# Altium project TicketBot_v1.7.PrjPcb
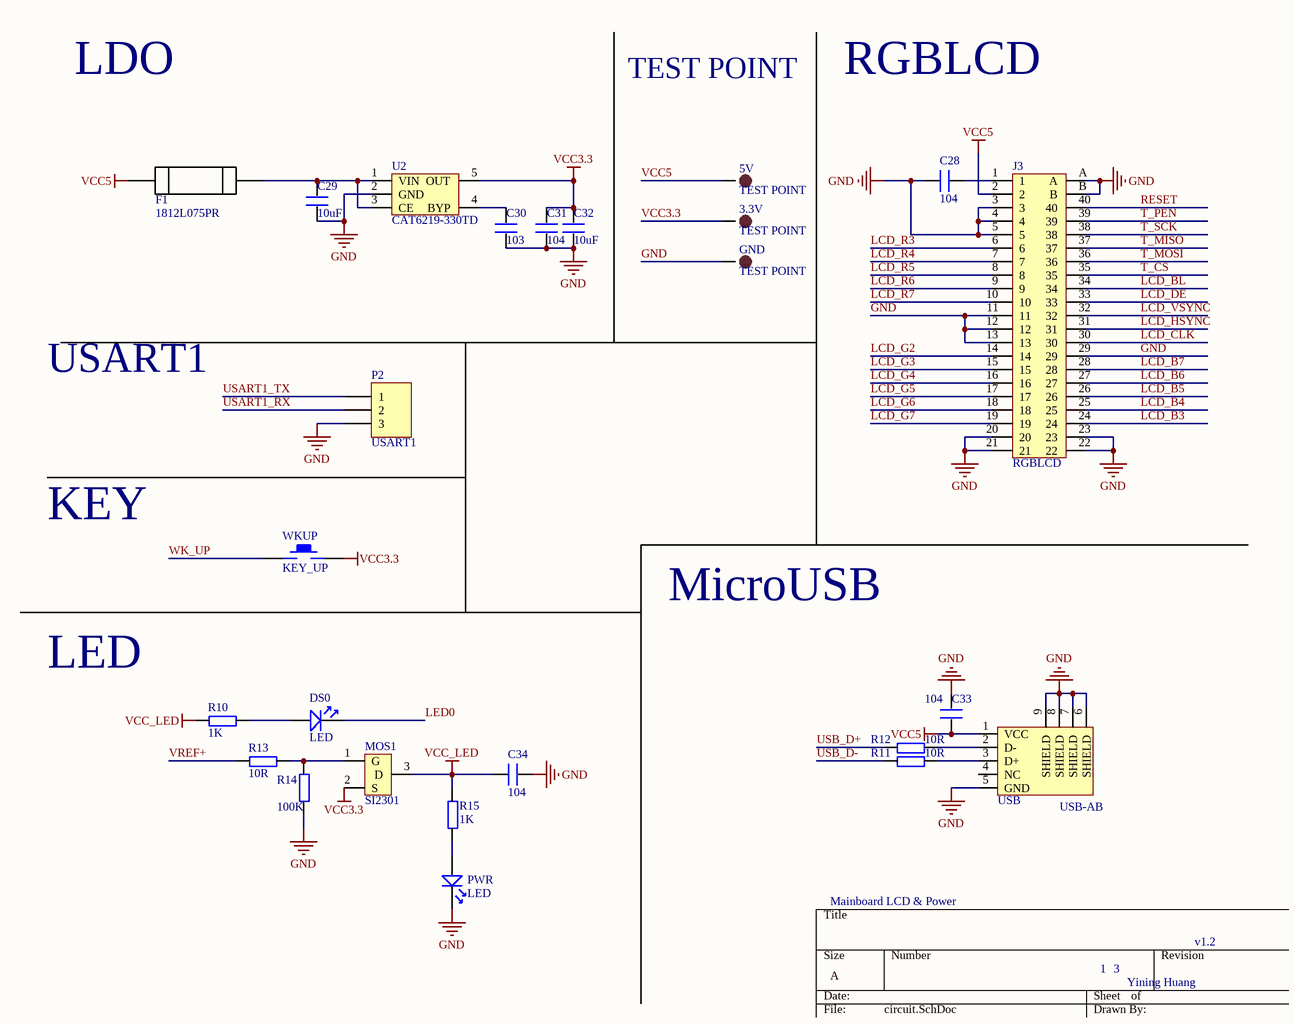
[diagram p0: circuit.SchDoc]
3 sheets, 90 parts. Net scope: global (net labels, ports and power ports of the same name join across sheets).
Board file: correctCore.PcbDoc
Sheets:
  circuit.SchDoc
  mem.SchDoc
  stm.SchDoc

## Sheet circuit.SchDoc
size A

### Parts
3.3V  TEST POINT  [TP-1.5]
5V  TEST POINT  [TP-1.5]
C28  104  [0805]
C29  10uF  [0805]
C30  103  [0805]
C31  104  [0805]
C32  10uF  [0805]
C33  104  [0805]
C34  104  [0805]
DS0  LED  [SMDLED-0603]
F1  1812L075PR  [*1812]
GND  TEST POINT  [TP-1.5]
J3  RGBLCD  [FPC-TOP40]
MOS1  SI2301  [SO-G3/C2.5]
P2  USART1  [HDR1X3]
PWR  LED  [SMDLED-0603]
R10  1K  [0805]
R11  10R  [0805]
R12  10R  [0805]
R13  10R  [0805]
R14  100K  [0805]
R15  1K  [0805]
U2  CAT6219-330TD  [SOT-23-5]
USB  USB-AB  [USB_AB - 5S - B]
WKUP  KEY_UP  [KEY_SOP3625]

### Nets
GND: C28.1 C29.1 C30.1 C31.1 C32.1 C33.2 C34.2 GND.1 J3.3 J3.4 J3.5 J3.11 J3.12 J3.13 J3.20 J3.21 J3.22 J3.23 J3.29 J3.A J3.B P2.3 PWR.2 R14.1 U2.2(GND) USB.5(GND) USB.6(SHIELD) USB.7(SHIELD) USB.8(SHIELD) USB.9(SHIELD)
VCC3.3: 3.3V.1 C31.2 C32.2 MOS1.2(S) U2.5(OUT) WKUP.2
VCC5: 5V.1 C33.1 F1.1 J3.2 USB.1(VCC)
VCC_LED: C34.1 MOS1.3(D) R10.1 R15.2
LCD_B3: J3.24
LCD_B4: J3.25
LCD_B5: J3.26
LCD_B6: J3.27
LCD_B7: J3.28
LCD_BL: J3.34
LCD_CLK: J3.30
LCD_DE: J3.33
LCD_G2: J3.14
LCD_G3: J3.15
LCD_G4: J3.16
LCD_G5: J3.17
LCD_G6: J3.18
LCD_G7: J3.19
LCD_HSYNC: J3.31
LCD_R3: J3.6
LCD_R4: J3.7
LCD_R5: J3.8
LCD_R6: J3.9
LCD_R7: J3.10
LCD_VSYNC: J3.32
LED0: DS0.2
RESET: J3.40
T_CS: J3.35  [project net PI8]
T_MISO: J3.37  [project net PG3]
T_MOSI: J3.36  [project net PI3]
T_PEN: J3.39  [project net PH7]
T_SCK: J3.38  [project net PH6]
USART1_RX: P2.2  [project net PA10]
USART1_TX: P2.1  [project net PA9]
USB_D+: R12.1  [project net PA12]
USB_D-: R11.1  [project net PA11]
VREF+: R13.1
WK_UP: WKUP.1  [project net PA0]
NetC28_2: C28.2 J3.1
NetC29_2: C29.2 F1.2 U2.1(VIN) U2.3(CE)
NetC30_2: C30.2 U2.4(BYP)
NetDS0_1: DS0.1 R10.2
NetMOS1_1: MOS1.1(G) R13.2 R14.2
NetPWR_1: PWR.1 R15.1
NetR11_2: R11.2 USB.3(D+)
NetR12_2: R12.2 USB.2(D-)

Not connected (* = marked no-connect by the designer): USB 4(NC)

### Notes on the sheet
- LDO
- TEST POINT
- RGBLCD
- USART1
- KEY
- MicroUSB
- LED
- Mainboard LCD & Power
- 1
- 3
- v1.2
- Yining Huang

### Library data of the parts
3.3V 5V GND = TEST-POINT: 测试点
C28-C34 = C
F1 = 1812L075PR: PTC Resettable Fuse 0.75A_hold_ 1.5A_trip_ 13.2VDC 100A 0.8W 0.2s 0.1Ohm SMD Solder Pad 1812 T/R; MF: Littelfuse Inc.
J3 = FPC-40: FPC-40P-0.5mm
MOS1 = MOS-P: IRLML6401/SI2301
P2 = Header 3: Header, 3-Pin
R10-R15 = R
U2 = CAT6219-330TD: 3.3V 500mA LDO
USB = USB-AB: MicroUSB
WKUP = KEY_M

## Sheet mem.SchDoc
size A
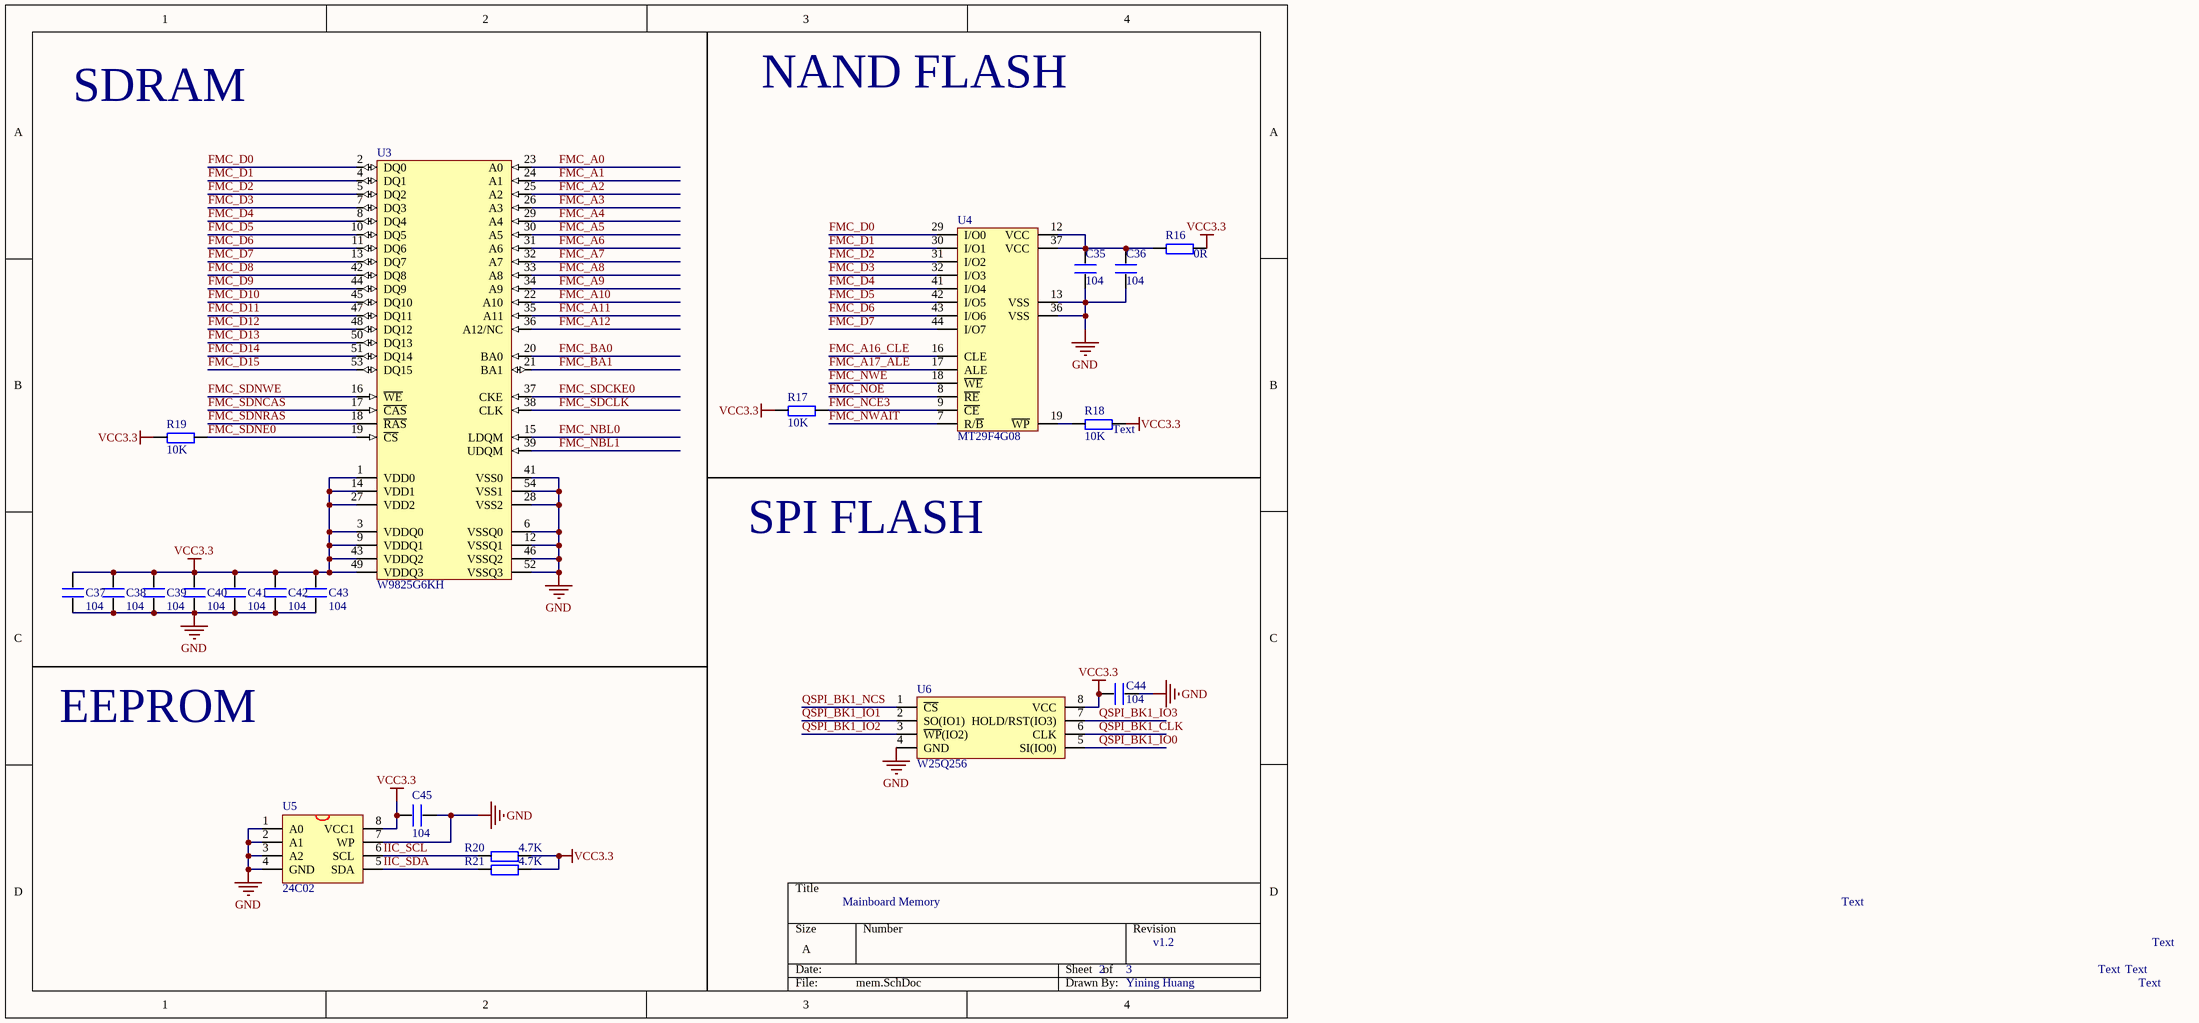
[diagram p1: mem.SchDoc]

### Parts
C35  104  [0805]
C36  104  [0805]
C37  104  [0805]
C38  104  [0805]
C39  104  [0805]
C40  104  [0805]
C41  104  [0805]
C42  104  [0805]
C43  104  [0805]
C44  104  [0805]
C45  104  [0805]
R16  0R  [0805]
R17  10K  [0805]
R18  10K  [0805]
R19  10K  [0805]
R20  4.7K  [0805]
R21  4.7K  [0805]
U3  W9825G6KH  [TSOP54]
U4  MT29F4G08  [TSOP48]
U5  24C02  [SOP-8]
U6  W25Q256  [WSON8]

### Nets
GND: C35.1 C36.1 C37.1 C38.1 C39.1 C40.1 C41.1 C42.1 C43.1 C44.2 C45.2 U3.6(VSSQ0) U3.12(VSSQ1) U3.28(VSS2) U3.41(VSS0) U3.46(VSSQ2) U3.52(VSSQ3) U3.54(VSS1) U4.13(VSS) U4.36(VSS) U5.1(A0) U5.2(A1) U5.3(A2) U5.4(GND) U5.7(WP) U6.4(GND)
VCC3.3: C37.2 C38.2 C39.2 C40.2 C41.2 C42.2 C43.2 C44.1 C45.1 R16.2 R17.1 R18.2 R19.1 R20.2 R21.2 U3.1(VDD0) U3.3(VDDQ0) U3.9(VDDQ1) U3.14(VDD1) U3.27(VDD2) U3.43(VDDQ2) U3.49(VDDQ3) U5.8(VCC1) U6.8(VCC)
FMC_A0: U3.23(A0)
FMC_A1: U3.24(A1)
FMC_A2: U3.25(A2)
FMC_A3: U3.26(A3)
FMC_A4: U3.29(A4)
FMC_A5: U3.30(A5)
FMC_A6: U3.31(A6)
FMC_A7: U3.32(A7)
FMC_A8: U3.33(A8)
FMC_A9: U3.34(A9)
FMC_A10: U3.22(A10)
FMC_A11: U3.35(A11)
FMC_A12: U3.36(A12/NC)
FMC_A16_CLE: U4.16(CLE)
FMC_A17_ALE: U4.17(ALE)
FMC_BA0: U3.20(BA0)
FMC_BA1: U3.21(BA1)
FMC_D0: U3.2(DQ0) U4.29(I/O0)
FMC_D1: U3.4(DQ1) U4.30(I/O1)
FMC_D2: U3.5(DQ2) U4.31(I/O2)
FMC_D3: U3.7(DQ3) U4.32(I/O3)
FMC_D4: U3.8(DQ4) U4.41(I/O4)
FMC_D5: U3.10(DQ5) U4.42(I/O5)
FMC_D6: U3.11(DQ6) U4.43(I/O6)
FMC_D7: U3.13(DQ7) U4.44(I/O7)
FMC_D8: U3.42(DQ8)
FMC_D9: U3.44(DQ9)
FMC_D10: U3.45(DQ10)
FMC_D11: U3.47(DQ11)
FMC_D12: U3.48(DQ12)
FMC_D13: U3.50(DQ13)
FMC_D14: U3.51(DQ14)
FMC_D15: U3.53(DQ15)
FMC_NBL0: U3.15(LDQM)
FMC_NBL1: U3.39(UDQM)
FMC_NCE3: R17.2 U4.9(~{CE})
FMC_NOE: U4.8(~{RE})
FMC_NWAIT: U4.7(R/~{B})
FMC_NWE: U4.18(~{WE})
FMC_SDCKE0: U3.37(CKE)
FMC_SDCLK: U3.38(CLK)
FMC_SDNCAS: U3.17(~{CAS})
FMC_SDNE0: R19.2 U3.19(~{CS})
FMC_SDNRAS: U3.18(~{RAS})
FMC_SDNWE: U3.16(~{WE})
IIC_SCL: R20.1 U5.6(SCL)
IIC_SDA: R21.1 U5.5(SDA)
QSPI_BK1_CLK: U6.6(CLK)  [project net PB2]
QSPI_BK1_IO0: U6.5(SI(IO0))  [project net PF8]
QSPI_BK1_IO1: U6.2(SO(IO1))  [project net PF9]
QSPI_BK1_IO2: U6.3(~{WP}(IO2))  [project net PF7]
QSPI_BK1_IO3: U6.7(HOLD/RST(IO3))  [project net PF6]
QSPI_BK1_NCS: U6.1(~{CS})  [project net PB6]
NetC35_2: C35.2 C36.2 R16.1 U4.12(VCC) U4.37(VCC)
NetR18_1: R18.1 U4.19(~{WP})

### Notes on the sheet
- NAND FLASH
- SDRAM
- (near R18) Text
- SPI FLASH
- EEPROM
- Mainboard Memory
- Text
- 2
- 3
- v1.2
- Yining Huang

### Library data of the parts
C35-C45 = C
R16-R21 = R
U3 = IS42S16160B: 32MB SDRAM
U4 = K9F2G08U0C: 256MB NAND FLASH
U5 = 24C256: EEPROM
U6 = W25Q128

## Sheet stm.SchDoc
size Tabloid
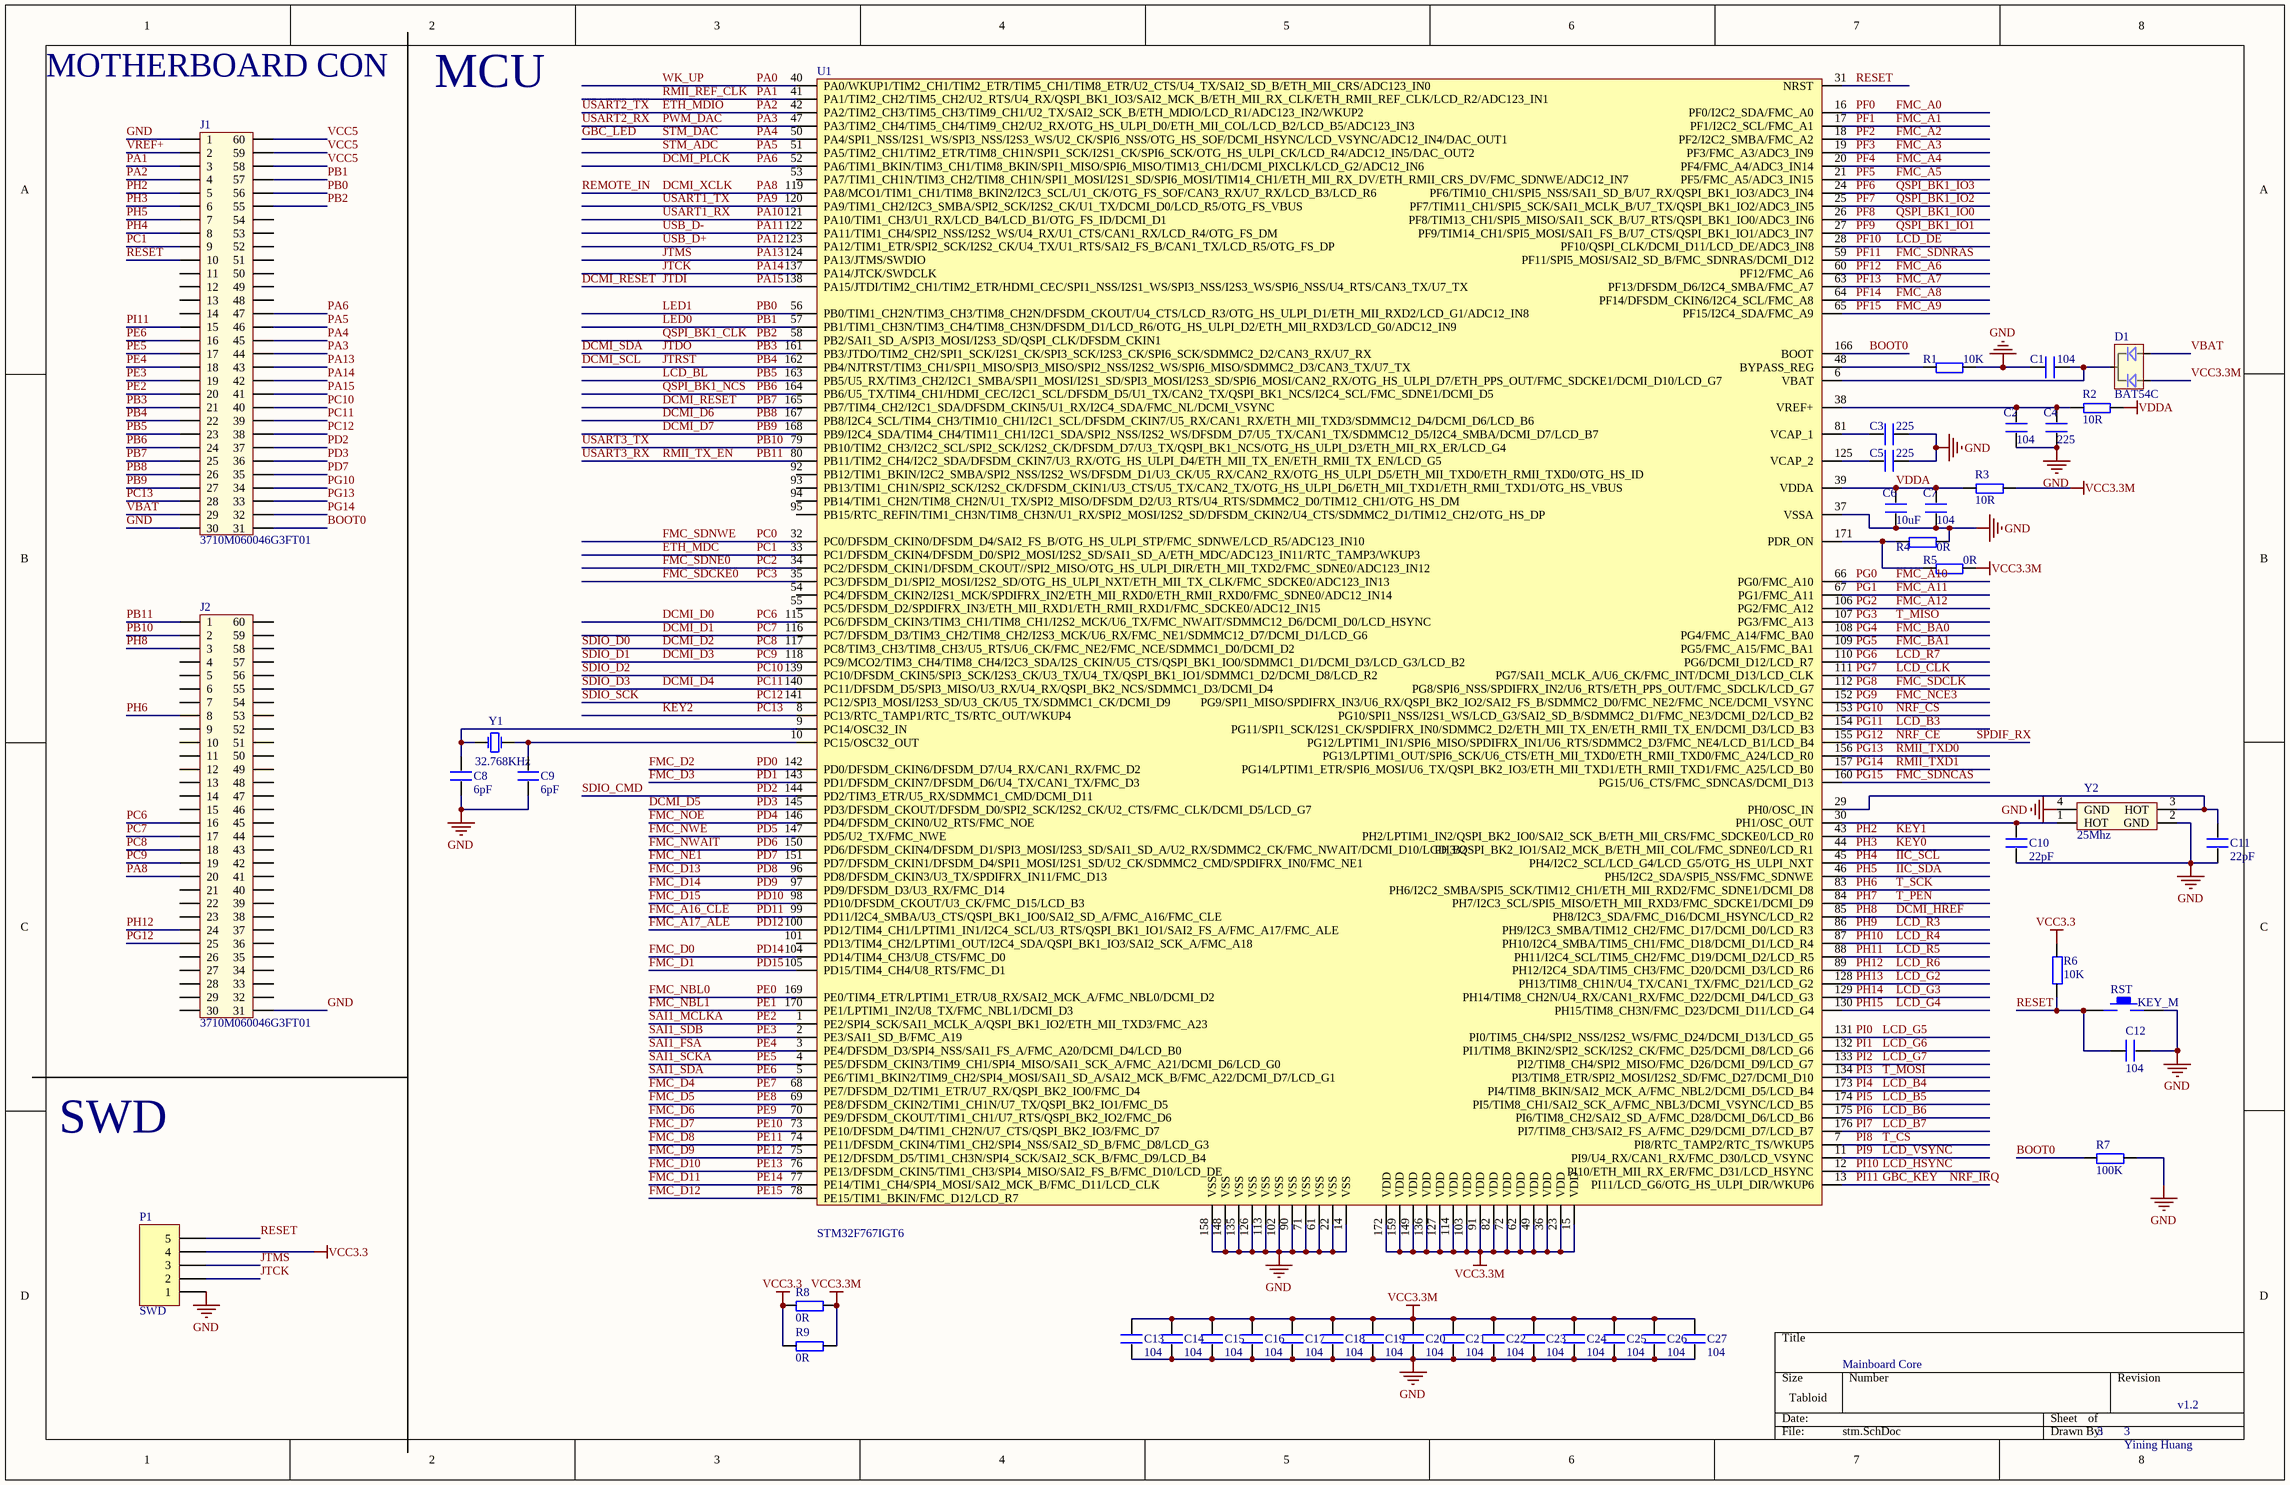
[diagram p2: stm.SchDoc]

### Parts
C1  104  [0805]
C2  104  [0805]
C3  225  [0805]
C4  225  [0805]
C5  225  [0805]
C6  10uF  [0805]
C7  104  [0805]
C8  6pF  [0805]
C9  6pF  [0805]
C10  22pF  [0805]
C11  22pF  [0805]
C12  104  [0805]
C13  104  [0805]
C14  104  [0805]
C15  104  [0805]
C16  104  [0805]
C17  104  [0805]
C18  104  [0805]
C19  104  [0805]
C20  104  [0805]
C21  104  [0805]
C22  104  [0805]
C23  104  [0805]
C24  104  [0805]
C25  104  [0805]
C26  104  [0805]
C27  104  [0805]
D1  BAT54C  [SOT-23]
J1  3710M060046G3FT01  [3710F060046G3FT01]
J2  3710M060046G3FT01  [3710F060046G3FT01]
P1  SWD  [HDR1X5]
R1  10K  [0805]
R2  10R  [0805]
R3  10R  [0805]
R4  0R  [0805]
R5  0R  [0805]
R6  10K  [0805]
R7  100K  [0805]
R8  0R  [0805]
R9  0R  [0805]
RST  KEY_M  [KEY_SOP3625]
U1  STM32F767IGT6  [LQFP176]
Y1  32.768KHz  [XTAL3215]
Y2  25Mhz  [XTAL3225]

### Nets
GND: C1.2 C2.1 C3.2 C4.1 C5.2 C6.1 C7.1 C8.1 C9.1 C10.1 C11.1 C12.2 C13.1 C14.1 C15.1 C16.1 C17.1 C18.1 C19.1 C20.1 C21.1 C22.1 C23.1 C24.1 C25.1 C26.1 C27.1 J1.1 J1.30 J2.31 P1.1 R1.2 R4.2 R7.2 RST.2 U1.14(VSS) U1.22(VSS) U1.37(VSSA) U1.61(VSS) U1.71(VSS) U1.90(VSS) U1.102(VSS) U1.113(VSS) U1.126(VSS) U1.135(VSS) U1.148(VSS) U1.158(VSS) Y2.2(GND) Y2.4(GND)
VCC3.3: P1.4 R6.2 R8.1 R9.1
VCC3.3M: C13.2 C14.2 C15.2 C16.2 C17.2 C18.2 C19.2 C20.2 C21.2 C22.2 C23.2 C24.2 C25.2 C26.2 C27.2 D1.1 R3.2 R5.2 R8.2 R9.2 U1.15(VDD) U1.23(VDD) U1.36(VDD) U1.49(VDD) U1.62(VDD) U1.72(VDD) U1.82(VDD) U1.91(VDD) U1.103(VDD) U1.114(VDD) U1.127(VDD) U1.136(VDD) U1.149(VDD) U1.159(VDD) U1.172(VDD)
VCC5: J1.58 J1.59 J1.60
VDDA: C6.2 C7.2 R2.2 R3.1 U1.39(VDDA)
BOOT0: J1.31 R7.1 U1.166(BOOT)
DCMI_D0: J2.16 U1.115(PC6/DFSDM_CKIN3/TIM3_CH1/TIM8_CH1/I2S2_MCK/U6_TX/FMC_NWAIT/SDMMC12_D6/DCMI_D0/LCD_HSYNC)  [also labelled PC6]
DCMI_D1: J2.17 U1.116(PC7/DFSDM_D3/TIM3_CH2/TIM8_CH2/I2S3_MCK/U6_RX/FMC_NE1/SDMMC12_D7/DCMI_D1/LCD_G6)  [also labelled PC7]
DCMI_D2: J2.18 U1.117(PC8/TIM3_CH3/TIM8_CH3/U5_RTS/U6_CK/FMC_NE2/FMC_NCE/SDMMC1_D0/DCMI_D2)  [also labelled PC8, SDIO_D0]
DCMI_D3: J2.19 U1.118(PC9/MCO2/TIM3_CH4/TIM8_CH4/I2C3_SDA/I2S_CKIN/U5_CTS/QSPI_BK1_IO0/SDMMC1_D1/DCMI_D3/LCD_G3/LCD_B2)  [also labelled PC9, SDIO_D1]
DCMI_D4: J1.39 U1.140(PC11/DFSDM_D5/SPI3_MISO/U3_RX/U4_RX/QSPI_BK2_NCS/SDMMC1_D3/DCMI_D4)  [also labelled PC11, SDIO_D3]
DCMI_D5: J1.36 U1.145(PD3/DFSDM_CKOUT/DFSDM_D0/SPI2_SCK/I2S2_CK/U2_CTS/FMC_CLK/DCMI_D5/LCD_G7)  [also labelled PD3]
DCMI_D6: J1.26 U1.167(PB8/I2C4_SCL/TIM4_CH3/TIM10_CH1/I2C1_SCL/DFSDM_CKIN7/U5_RX/CAN1_RX/ETH_MII_TXD3/SDMMC12_D4/DCMI_D6/LCD_B6)  [also labelled PB8]
DCMI_D7: J1.27 U1.168(PB9/I2C4_SDA/TIM4_CH4/TIM11_CH1/I2C1_SDA/SPI2_NSS/I2S2_WS/DFSDM_D7/U5_TX/CAN1_TX/SDMMC12_D5/I2C4_SMBA/DCMI_D7/LCD_B7)  [also labelled PB9]
DCMI_HREF: J2.3 U1.85(PH8/I2C3_SDA/FMC_D16/DCMI_HSYNC/LCD_R2)  [also labelled PH8]
DCMI_PLCK: J1.47 U1.52(PA6/TIM1_BKIN/TIM3_CH1/TIM8_BKIN/SPI1_MISO/SPI6_MISO/TIM13_CH1/DCMI_PIXCLK/LCD_G2/ADC12_IN6)  [also labelled PA6]
DCMI_RESET: J1.25 J1.41 U1.138(PA15/JTDI/TIM2_CH1/TIM2_ETR/HDMI_CEC/SPI1_NSS/I2S1_WS/SPI3_NSS/I2S3_WS/SPI6_NSS/U4_RTS/CAN3_TX/U7_TX) U1.165(PB7/TIM4_CH2/I2C1_SDA/DFSDM_CKIN5/U1_RX/I2C4_SDA/FMC_NL/DCMI_VSYNC)  [also labelled JTDI, PA15, PB7]
DCMI_SCL: J1.22 U1.162(PB4/NJTRST/TIM3_CH1/SPI1_MISO/SPI3_MISO/SPI2_NSS/I2S2_WS/SPI6_MISO/SDMMC2_D3/CAN3_TX/U7_TX)  [also labelled JTRST, PB4]
DCMI_SDA: J1.21 U1.161(PB3/JTDO/TIM2_CH2/SPI1_SCK/I2S1_CK/SPI3_SCK/I2S3_CK/SPI6_SCK/SDMMC2_D2/CAN3_RX/U7_RX)  [also labelled JTDO, PB3]
DCMI_XCLK: J2.20 U1.119(PA8/MCO1/TIM1_CH1/TIM8_BKIN2/I2C3_SCL/U1_CK/OTG_FS_SOF/CAN3_RX/U7_RX/LCD_B3/LCD_R6)  [also labelled PA8, REMOTE_IN]
ETH_MDC: J1.9 U1.33(PC1/DFSDM_CKIN4/DFSDM_D0/SPI2_MOSI/I2S2_SD/SAI1_SD_A/ETH_MDC/ADC123_IN11/RTC_TAMP3/WKUP3)  [also labelled PC1]
ETH_MDIO: J1.4 U1.42(PA2/TIM2_CH3/TIM5_CH3/TIM9_CH1/U2_TX/SAI2_SCK_B/ETH_MDIO/LCD_R1/ADC123_IN2/WKUP2)  [also labelled PA2, USART2_TX]
FMC_A0: U1.16(PF0/I2C2_SDA/FMC_A0)  [also labelled PF0]
FMC_A1: U1.17(PF1/I2C2_SCL/FMC_A1)  [also labelled PF1]
FMC_A2: U1.18(PF2/I2C2_SMBA/FMC_A2)  [also labelled PF2]
FMC_A3: U1.19(PF3/FMC_A3/ADC3_IN9)  [also labelled PF3]
FMC_A4: U1.20(PF4/FMC_A4/ADC3_IN14)  [also labelled PF4]
FMC_A5: U1.21(PF5/FMC_A5/ADC3_IN15)  [also labelled PF5]
FMC_A6: U1.60(PF12/FMC_A6)  [also labelled PF12]
FMC_A7: U1.63(PF13/DFSDM_D6/I2C4_SMBA/FMC_A7)  [also labelled PF13]
FMC_A8: U1.64(PF14/DFSDM_CKIN6/I2C4_SCL/FMC_A8)  [also labelled PF14]
FMC_A9: U1.65(PF15/I2C4_SDA/FMC_A9)  [also labelled PF15]
FMC_A10: U1.66(PG0/FMC_A10)  [also labelled PG0]
FMC_A11: U1.67(PG1/FMC_A11)  [also labelled PG1]
FMC_A12: U1.106(PG2/FMC_A12)  [also labelled PG2]
FMC_A16_CLE: U1.99(PD11/I2C4_SMBA/U3_CTS/QSPI_BK1_IO0/SAI2_SD_A/FMC_A16/FMC_CLE)  [also labelled PD11]
FMC_A17_ALE: U1.100(PD12/TIM4_CH1/LPTIM1_IN1/I2C4_SCL/U3_RTS/QSPI_BK1_IO1/SAI2_FS_A/FMC_A17/FMC_ALE)  [also labelled PD12]
FMC_BA0: U1.108(PG4/FMC_A14/FMC_BA0)  [also labelled PG4]
FMC_BA1: U1.109(PG5/FMC_A15/FMC_BA1)  [also labelled PG5]
FMC_D0: U1.104(PD14/TIM4_CH3/U8_CTS/FMC_D0)  [also labelled PD14]
FMC_D1: U1.105(PD15/TIM4_CH4/U8_RTS/FMC_D1)  [also labelled PD15]
FMC_D2: U1.142(PD0/DFSDM_CKIN6/DFSDM_D7/U4_RX/CAN1_RX/FMC_D2)  [also labelled PD0]
FMC_D3: U1.143(PD1/DFSDM_CKIN7/DFSDM_D6/U4_TX/CAN1_TX/FMC_D3)  [also labelled PD1]
FMC_D4: U1.68(PE7/DFSDM_D2/TIM1_ETR/U7_RX/QSPI_BK2_IO0/FMC_D4)  [also labelled PE7]
FMC_D5: U1.69(PE8/DFSDM_CKIN2/TIM1_CH1N/U7_TX/QSPI_BK2_IO1/FMC_D5)  [also labelled PE8]
FMC_D6: U1.70(PE9/DFSDM_CKOUT/TIM1_CH1/U7_RTS/QSPI_BK2_IO2/FMC_D6)  [also labelled PE9]
FMC_D7: U1.73(PE10/DFSDM_D4/TIM1_CH2N/U7_CTS/QSPI_BK2_IO3/FMC_D7)  [also labelled PE10]
FMC_D8: U1.74(PE11/DFSDM_CKIN4/TIM1_CH2/SPI4_NSS/SAI2_SD_B/FMC_D8/LCD_G3)  [also labelled PE11]
FMC_D9: U1.75(PE12/DFSDM_D5/TIM1_CH3N/SPI4_SCK/SAI2_SCK_B/FMC_D9/LCD_B4)  [also labelled PE12]
FMC_D10: U1.76(PE13/DFSDM_CKIN5/TIM1_CH3/SPI4_MISO/SAI2_FS_B/FMC_D10/LCD_DE)  [also labelled PE13]
FMC_D11: U1.77(PE14/TIM1_CH4/SPI4_MOSI/SAI2_MCK_B/FMC_D11/LCD_CLK)  [also labelled PE14]
FMC_D12: U1.78(PE15/TIM1_BKIN/FMC_D12/LCD_R7)  [also labelled PE15]
FMC_D13: U1.96(PD8/DFSDM_CKIN3/U3_TX/SPDIFRX_IN11/FMC_D13)  [also labelled PD8]
FMC_D14: U1.97(PD9/DFSDM_D3/U3_RX/FMC_D14)  [also labelled PD9]
FMC_D15: U1.98(PD10/DFSDM_CKOUT/U3_CK/FMC_D15/LCD_B3)  [also labelled PD10]
FMC_NBL0: U1.169(PE0/TIM4_ETR/LPTIM1_ETR/U8_RX/SAI2_MCK_A/FMC_NBL0/DCMI_D2)  [also labelled PE0]
FMC_NBL1: U1.170(PE1/LPTIM1_IN2/U8_TX/FMC_NBL1/DCMI_D3)  [also labelled PE1]
FMC_NCE3: U1.152(PG9/SPI1_MISO/SPDIFRX_IN3/U6_RX/QSPI_BK2_IO2/SAI2_FS_B/SDMMC2_D0/FMC_NE2/FMC_NCE/DCMI_VSYNC)  [also labelled PG9]
FMC_NE1: J1.35 U1.151(PD7/DFSDM_CKIN1/DFSDM_D4/SPI1_MOSI/I2S1_SD/U2_CK/SDMMC2_CMD/SPDIFRX_IN0/FMC_NE1)  [also labelled PD7]
FMC_NOE: U1.146(PD4/DFSDM_CKIN0/U2_RTS/FMC_NOE)  [also labelled PD4]
FMC_NWAIT: U1.150(PD6/DFSDM_CKIN4/DFSDM_D1/SPI3_MOSI/I2S3_SD/SAI1_SD_A/U2_RX/SDMMC2_CK/FMC_NWAIT/DCMI_D10/LCD_B2)  [also labelled PD6]
FMC_NWE: U1.147(PD5/U2_TX/FMC_NWE)  [also labelled PD5]
FMC_SDCKE0: U1.35(PC3/DFSDM_D1/SPI2_MOSI/I2S2_SD/OTG_HS_ULPI_NXT/ETH_MII_TX_CLK/FMC_SDCKE0/ADC123_IN13)  [also labelled PC3]
FMC_SDCLK: U1.112(PG8/SPI6_NSS/SPDIFRX_IN2/U6_RTS/ETH_PPS_OUT/FMC_SDCLK/LCD_G7)  [also labelled PG8]
FMC_SDNCAS: U1.160(PG15/U6_CTS/FMC_SDNCAS/DCMI_D13)  [also labelled PG15]
FMC_SDNE0: U1.34(PC2/DFSDM_CKIN1/DFSDM_CKOUT//SPI2_MISO/OTG_HS_ULPI_DIR/ETH_MII_TXD2/FMC_SDNE0/ADC123_IN12)  [also labelled PC2]
FMC_SDNRAS: U1.59(PF11/SPI5_MOSI/SAI2_SD_B/FMC_SDNRAS/DCMI_D12)  [also labelled PF11]
FMC_SDNWE: U1.32(PC0/DFSDM_CKIN0/DFSDM_D4/SAI2_FS_B/OTG_HS_ULPI_STP/FMC_SDNWE/LCD_R5/ADC123_IN10)  [also labelled PC0]
GBC_KEY: J1.15 U1.13(PI11/LCD_G6/OTG_HS_ULPI_DIR/WKUP6)  [also labelled NRF_IRQ, PI11]
GBC_LED: J1.45 U1.50(PA4/SPI1_NSS/I2S1_WS/SPI3_NSS/I2S3_WS/U2_CK/SPI6_NSS/OTG_HS_SOF/DCMI_HSYNC/LCD_VSYNC/ADC12_IN4/DAC_OUT1)  [also labelled PA4, STM_DAC]
IIC_SCL: J1.8 U1.45(PH4/I2C2_SCL/LCD_G4/LCD_G5/OTG_HS_ULPI_NXT)  [also labelled PH4]
IIC_SDA: J1.7 U1.46(PH5/I2C2_SDA/SPI5_NSS/FMC_SDNWE)  [also labelled PH5]
JTCK: J1.42 P1.2 U1.137(PA14/JTCK/SWDCLK)  [also labelled PA14]
JTMS: J1.43 P1.3 U1.124(PA13/JTMS/SWDIO)  [also labelled PA13]
KEY0: J1.6 U1.44(PH3/QSPI_BK2_IO1/SAI2_MCK_B/ETH_MII_COL/FMC_SDNE0/LCD_R1)  [also labelled PH3]
KEY1: J1.5 U1.43(PH2/LPTIM1_IN2/QSPI_BK2_IO0/SAI2_SCK_B/ETH_MII_CRS/FMC_SDCKE0/LCD_R0)  [also labelled PH2]
KEY2: J1.28 U1.8(PC13/RTC_TAMP1/RTC_TS/RTC_OUT/WKUP4)  [also labelled PC13]
LCD_B3: U1.154(PG11/SPI1_SCK/I2S1_CK/SPDIFRX_IN0/SDMMC2_D2/ETH_MII_TX_EN/ETH_RMII_TX_EN/DCMI_D3/LCD_B3)  [also labelled PG11]
LCD_B4: U1.173(PI4/TIM8_BKIN/SAI2_MCK_A/FMC_NBL2/DCMI_D5/LCD_B4)  [also labelled PI4]
LCD_B5: U1.174(PI5/TIM8_CH1/SAI2_SCK_A/FMC_NBL3/DCMI_VSYNC/LCD_B5)  [also labelled PI5]
LCD_B6: U1.175(PI6/TIM8_CH2/SAI2_SD_A/FMC_D28/DCMI_D6/LCD_B6)  [also labelled PI6]
LCD_B7: U1.176(PI7/TIM8_CH3/SAI2_FS_A/FMC_D29/DCMI_D7/LCD_B7)  [also labelled PI7]
LCD_BL: J1.23 U1.163(PB5/U5_RX/TIM3_CH2/I2C1_SMBA/SPI1_MOSI/I2S1_SD/SPI3_MOSI/I2S3_SD/SPI6_MOSI/CAN2_RX/OTG_HS_ULPI_D7/ETH_PPS_OUT/FMC_SDCKE1/DCMI_D10/LCD_G7)  [also labelled PB5]
LCD_CLK: U1.111(PG7/SAI1_MCLK_A/U6_CK/FMC_INT/DCMI_D13/LCD_CLK)  [also labelled PG7]
LCD_DE: U1.28(PF10/QSPI_CLK/DCMI_D11/LCD_DE/ADC3_IN8)  [also labelled PF10]
LCD_G2: U1.128(PH13/TIM8_CH1N/U4_TX/CAN1_TX/FMC_D21/LCD_G2)  [also labelled PH13]
LCD_G3: U1.129(PH14/TIM8_CH2N/U4_RX/CAN1_RX/FMC_D22/DCMI_D4/LCD_G3)  [also labelled PH14]
LCD_G4: U1.130(PH15/TIM8_CH3N/FMC_D23/DCMI_D11/LCD_G4)  [also labelled PH15]
LCD_G5: U1.131(PI0/TIM5_CH4/SPI2_NSS/I2S2_WS/FMC_D24/DCMI_D13/LCD_G5)  [also labelled PI0]
LCD_G6: U1.132(PI1/TIM8_BKIN2/SPI2_SCK/I2S2_CK/FMC_D25/DCMI_D8/LCD_G6)  [also labelled PI1]
LCD_G7: U1.133(PI2/TIM8_CH4/SPI2_MISO/FMC_D26/DCMI_D9/LCD_G7)  [also labelled PI2]
LCD_HSYNC: U1.12(PI10/ETH_MII_RX_ER/FMC_D31/LCD_HSYNC)  [also labelled PI10]
LCD_R3: U1.86(PH9/I2C3_SMBA/TIM12_CH2/FMC_D17/DCMI_D0/LCD_R3)  [also labelled PH9]
LCD_R4: U1.87(PH10/I2C4_SMBA/TIM5_CH1/FMC_D18/DCMI_D1/LCD_R4)  [also labelled PH10]
LCD_R5: U1.88(PH11/I2C4_SCL/TIM5_CH2/FMC_D19/DCMI_D2/LCD_R5)  [also labelled PH11]
LCD_R6: J2.24 U1.89(PH12/I2C4_SDA/TIM5_CH3/FMC_D20/DCMI_D3/LCD_R6)  [also labelled PH12]
LCD_R7: U1.110(PG6/DCMI_D12/LCD_R7)  [also labelled PG6]
LCD_VSYNC: U1.11(PI9/U4_RX/CAN1_RX/FMC_D30/LCD_VSYNC)  [also labelled PI9]
LED0: J1.57 U1.57(PB1/TIM1_CH3N/TIM3_CH4/TIM8_CH3N/DFSDM_D1/LCD_R6/OTG_HS_ULPI_D2/ETH_MII_RXD3/LCD_G0/ADC12_IN9)  [also labelled PB1]
LED1: J1.56 U1.56(PB0/TIM1_CH2N/TIM3_CH3/TIM8_CH2N/DFSDM_CKOUT/U4_CTS/LCD_R3/OTG_HS_ULPI_D1/ETH_MII_RXD2/LCD_G1/ADC12_IN8)  [also labelled PB0]
NRF_CE: J2.25 U1.155(PG12/LPTIM1_IN1/SPI6_MISO/SPDIFRX_IN1/U6_RTS/SDMMC2_D3/FMC_NE4/LCD_B1/LCD_B4)  [also labelled PG12, SPDIF_RX]
NRF_CS: J1.34 U1.153(PG10/SPI1_NSS/I2S1_WS/LCD_G3/SAI2_SD_B/SDMMC2_D1/FMC_NE3/DCMI_D2/LCD_B2)  [also labelled PG10]
PA0: U1.40(PA0/WKUP1/TIM2_CH1/TIM2_ETR/TIM5_CH1/TIM8_ETR/U2_CTS/U4_TX/SAI2_SD_B/ETH_MII_CRS/ADC123_IN0)  [also labelled WK_UP]
PA1: J1.3 U1.41(PA1/TIM2_CH2/TIM5_CH2/U2_RTS/U4_RX/QSPI_BK1_IO3/SAI2_MCK_B/ETH_MII_RX_CLK/ETH_RMII_REF_CLK/LCD_R2/ADC123_IN1)  [also labelled RMII_REF_CLK]
PA3: J1.44 U1.47(PA3/TIM2_CH4/TIM5_CH4/TIM9_CH2/U2_RX/OTG_HS_ULPI_D0/ETH_MII_COL/LCD_B2/LCD_B5/ADC123_IN3)  [also labelled PWM_DAC, USART2_RX]
PA5: J1.46 U1.51(PA5/TIM2_CH1/TIM2_ETR/TIM8_CH1N/SPI1_SCK/I2S1_CK/SPI6_SCK/OTG_HS_ULPI_CK/LCD_R4/ADC12_IN5/DAC_OUT2)  [also labelled STM_ADC]
PA9: U1.120(PA9/TIM1_CH2/I2C3_SMBA/SPI2_SCK/I2S2_CK/U1_TX/DCMI_D0/LCD_R5/OTG_FS_VBUS)  [also labelled USART1_TX]
PA10: U1.121(PA10/TIM1_CH3/U1_RX/LCD_B4/LCD_B1/OTG_FS_ID/DCMI_D1)  [also labelled USART1_RX]
PA11: U1.122(PA11/TIM1_CH4/SPI2_NSS/I2S2_WS/U4_RX/U1_CTS/CAN1_RX/LCD_R4/OTG_FS_DM)  [also labelled USB_D-]
PA12: U1.123(PA12/TIM1_ETR/SPI2_SCK/I2S2_CK/U4_TX/U1_RTS/SAI2_FS_B/CAN1_TX/LCD_R5/OTG_FS_DP)  [also labelled USB_D+]
PB2: J1.55 U1.58(PB2/SAI1_SD_A/SPI3_MOSI/I2S3_SD/QSPI_CLK/DFSDM_CKIN1)  [also labelled QSPI_BK1_CLK]
PB6: J1.24 U1.164(PB6/U5_TX/TIM4_CH1/HDMI_CEC/I2C1_SCL/DFSDM_D5/U1_TX/CAN2_TX/QSPI_BK1_NCS/I2C4_SCL/FMC_SDNE1/DCMI_D5)  [also labelled QSPI_BK1_NCS]
PB10: J2.2 U1.79(PB10/TIM2_CH3/I2C2_SCL/SPI2_SCK/I2S2_CK/DFSDM_D7/U3_TX/QSPI_BK1_NCS/OTG_HS_ULPI_D3/ETH_MII_RX_ER/LCD_G4)  [also labelled USART3_TX]
PB11: J2.1 U1.80(PB11/TIM2_CH4/I2C2_SDA/DFSDM_CKIN7/U3_RX/OTG_HS_ULPI_D4/ETH_MII_TX_EN/ETH_RMII_TX_EN/LCD_G5)  [also labelled RMII_TX_EN, USART3_RX]
PC10: J1.40 U1.139(PC10/DFSDM_CKIN5/SPI3_SCK/I2S3_CK/U3_TX/U4_TX/QSPI_BK1_IO1/SDMMC1_D2/DCMI_D8/LCD_R2)  [also labelled SDIO_D2]
PC12: J1.38 U1.141(PC12/SPI3_MOSI/I2S3_SD/U3_CK/U5_TX/SDMMC1_CK/DCMI_D9)  [also labelled SDIO_SCK]
PD2: J1.37 U1.144(PD2/TIM3_ETR/U5_RX/SDMMC1_CMD/DCMI_D11)  [also labelled SDIO_CMD]
PE2: J1.20 U1.1(PE2/SPI4_SCK/SAI1_MCLK_A/QSPI_BK1_IO2/ETH_MII_TXD3/FMC_A23)  [also labelled SAI1_MCLKA]
PE3: J1.19 U1.2(PE3/SAI1_SD_B/FMC_A19)  [also labelled SAI1_SDB]
PE4: J1.18 U1.3(PE4/DFSDM_D3/SPI4_NSS/SAI1_FS_A/FMC_A20/DCMI_D4/LCD_B0)  [also labelled SAI1_FSA]
PE5: J1.17 U1.4(PE5/DFSDM_CKIN3/TIM9_CH1/SPI4_MISO/SAI1_SCK_A/FMC_A21/DCMI_D6/LCD_G0)  [also labelled SAI1_SCKA]
PE6: J1.16 U1.5(PE6/TIM1_BKIN2/TIM9_CH2/SPI4_MOSI/SAI1_SD_A/SAI2_MCK_B/FMC_A22/DCMI_D7/LCD_G1)  [also labelled SAI1_SDA]
PF6: U1.24(PF6/TIM10_CH1/SPI5_NSS/SAI1_SD_B/U7_RX/QSPI_BK1_IO3/ADC3_IN4)  [also labelled QSPI_BK1_IO3]
PF7: U1.25(PF7/TIM11_CH1/SPI5_SCK/SAI1_MCLK_B/U7_TX/QSPI_BK1_IO2/ADC3_IN5)  [also labelled QSPI_BK1_IO2]
PF8: U1.26(PF8/TIM13_CH1/SPI5_MISO/SAI1_SCK_B/U7_RTS/QSPI_BK1_IO0/ADC3_IN6)  [also labelled QSPI_BK1_IO0]
PF9: U1.27(PF9/TIM14_CH1/SPI5_MOSI/SAI1_FS_B/U7_CTS/QSPI_BK1_IO1/ADC3_IN7)  [also labelled QSPI_BK1_IO1]
PG3: U1.107(PG3/FMC_A13)  [also labelled T_MISO]
PG13: J1.33 U1.156(PG13/LPTIM1_OUT/SPI6_SCK/U6_CTS/ETH_MII_TXD0/ETH_RMII_TXD0/FMC_A24/LCD_R0)  [also labelled RMII_TXD0]
PG14: J1.32 U1.157(PG14/LPTIM1_ETR/SPI6_MOSI/U6_TX/QSPI_BK2_IO3/ETH_MII_TXD1/ETH_RMII_TXD1/FMC_A25/LCD_B0)  [also labelled RMII_TXD1]
PH6: J2.8 U1.83(PH6/I2C2_SMBA/SPI5_SCK/TIM12_CH1/ETH_MII_RXD2/FMC_SDNE1/DCMI_D8)  [also labelled T_SCK]
PH7: U1.84(PH7/I2C3_SCL/SPI5_MISO/ETH_MII_RXD3/FMC_SDCKE1/DCMI_D9)  [also labelled T_PEN]
PI3: U1.134(PI3/TIM8_ETR/SPI2_MOSI/I2S2_SD/FMC_D27/DCMI_D10)  [also labelled T_MOSI]
PI8: U1.7(PI8/RTC_TAMP2/RTC_TS/WKUP5)  [also labelled T_CS]
RESET: C12.1 J1.10 P1.5 R6.1 RST.1 U1.31(NRST)
VBAT: D1.2 J1.29
VREF+: J1.2
NetC1_1: C1.1 D1.3 U1.6(VBAT)
NetC2_2: C2.2 C4.2 R2.1 U1.38(VREF+)
NetC3_1: C3.1 U1.81(VCAP_1)
NetC5_1: C5.1 U1.125(VCAP_2)
NetC8_2: C8.2 U1.9(PC14/OSC32_IN) Y1.1(OSC1)
NetC9_2: C9.2 U1.10(PC15/OSC32_OUT) Y1.2(OSC2)
NetC10_2: C10.2 U1.30(PH1/OSC_OUT) Y2.1(HOT)
NetC11_2: C11.2 U1.29(PH0/OSC_IN) Y2.3(HOT)
NetR1_1: R1.1 U1.48(BYPASS_REG)
NetR4_1: R4.1 R5.1 U1.171(PDR_ON)

Not connected (* = marked no-connect by the designer): J1 11 12 13 14 48 49 50 51 52 53 54; J2 4 5 6 7 9 10 11 12 13 14 15 21 22 23 26 27 28 29 30 32 33 34 35 36 37 38 39 40 41 42 43 44 45 46 47 48 49 50 51 52 53 54 55 56 57 58 59 60; U1 53(PA7/TIM1_CH1N/TIM3_CH2/TIM8_CH1N/SPI1_MOSI/I2S1_SD/SPI6_MOSI/TIM14_CH1/ETH_MII_RX_DV/ETH_RMII_CRS_DV/FMC_SDNWE/ADC12_IN7) 54(PC4/DFSDM_CKIN2/I2S1_MCK/SPDIFRX_IN2/ETH_MII_RXD0/ETH_RMII_RXD0/FMC_SDNE0/ADC12_IN14) 55(PC5/DFSDM_D2/SPDIFRX_IN3/ETH_MII_RXD1/ETH_RMII_RXD1/FMC_SDCKE0/ADC12_IN15) 92(PB12/TIM1_BKIN/I2C2_SMBA/SPI2_NSS/I2S2_WS/DFSDM_D1/U3_CK/U5_RX/CAN2_RX/OTG_HS_ULPI_D5/ETH_MII_TXD0/ETH_RMII_TXD0/OTG_HS_ID) 93(PB13/TIM1_CH1N/SPI2_SCK/I2S2_CK/DFSDM_CKIN1/U3_CTS/U5_TX/CAN2_TX/OTG_HS_ULPI_D6/ETH_MII_TXD1/ETH_RMII_TXD1/OTG_HS_VBUS) 94(PB14/TIM1_CH2N/TIM8_CH2N/U1_TX/SPI2_MISO/DFSDM_D2/U3_RTS/U4_RTS/SDMMC2_D0/TIM12_CH1/OTG_HS_DM) 95(PB15/RTC_REFIN/TIM1_CH3N/TIM8_CH3N/U1_RX/SPI2_MOSI/I2S2_SD/DFSDM_CKIN2/U4_CTS/SDMMC2_D1/TIM12_CH2/OTG_HS_DP) 101(PD13/TIM4_CH2/LPTIM1_OUT/I2C4_SDA/QSPI_BK1_IO3/SAI2_SCK_A/FMC_A18)

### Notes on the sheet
- MOTHERBOARD CON
- MCU
- SWD
- Mainboard Core
- 3
- v1.2
- Yining Huang

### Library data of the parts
C1-C27 = C
D1 = BAT54C: 双肖特基二极管
J1 J2 = 3710F: 3710F060046G3FT01
P1 = Header 5: Header, 5-Pin
R1-R9 = R
Y1 = XTAL: 普通晶振
Y2 = XTAL_3225: 3225贴片无源晶振

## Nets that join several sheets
GND: circuit (30 pins), mem (26 pins), stm (49 pins)
VCC3.3: circuit (6 pins), mem (24 pins), stm (P1.4 R6.2 R8.1 R9.1)
VCC5: circuit (5 pins), stm (J1.58 J1.59 J1.60)
FMC_A0: mem (U3.23), stm (U1.16)
FMC_A1: mem (U3.24), stm (U1.17)
FMC_A2: mem (U3.25), stm (U1.18)
FMC_A3: mem (U3.26), stm (U1.19)
FMC_A4: mem (U3.29), stm (U1.20)
FMC_A5: mem (U3.30), stm (U1.21)
FMC_A6: mem (U3.31), stm (U1.60)
FMC_A7: mem (U3.32), stm (U1.63)
FMC_A8: mem (U3.33), stm (U1.64)
FMC_A9: mem (U3.34), stm (U1.65)
FMC_A10: mem (U3.22), stm (U1.66)
FMC_A11: mem (U3.35), stm (U1.67)
FMC_A12: mem (U3.36), stm (U1.106)
FMC_A16_CLE: mem (U4.16), stm (U1.99)
FMC_A17_ALE: mem (U4.17), stm (U1.100)
FMC_BA0: mem (U3.20), stm (U1.108)
FMC_BA1: mem (U3.21), stm (U1.109)
FMC_D0: mem (U3.2 U4.29), stm (U1.104)
FMC_D1: mem (U3.4 U4.30), stm (U1.105)
FMC_D2: mem (U3.5 U4.31), stm (U1.142)
FMC_D3: mem (U3.7 U4.32), stm (U1.143)
FMC_D4: mem (U3.8 U4.41), stm (U1.68)
FMC_D5: mem (U3.10 U4.42), stm (U1.69)
FMC_D6: mem (U3.11 U4.43), stm (U1.70)
FMC_D7: mem (U3.13 U4.44), stm (U1.73)
FMC_D8: mem (U3.42), stm (U1.74)
FMC_D9: mem (U3.44), stm (U1.75)
FMC_D10: mem (U3.45), stm (U1.76)
FMC_D11: mem (U3.47), stm (U1.77)
FMC_D12: mem (U3.48), stm (U1.78)
FMC_D13: mem (U3.50), stm (U1.96)
FMC_D14: mem (U3.51), stm (U1.97)
FMC_D15: mem (U3.53), stm (U1.98)
FMC_NBL0: mem (U3.15), stm (U1.169)
FMC_NBL1: mem (U3.39), stm (U1.170)
FMC_NCE3: mem (R17.2 U4.9), stm (U1.152)
FMC_NOE: mem (U4.8), stm (U1.146)
FMC_NWAIT: mem (U4.7), stm (U1.150)
FMC_NWE: mem (U4.18), stm (U1.147)
FMC_SDCKE0: mem (U3.37), stm (U1.35)
FMC_SDCLK: mem (U3.38), stm (U1.112)
FMC_SDNCAS: mem (U3.17), stm (U1.160)
FMC_SDNE0: mem (R19.2 U3.19), stm (U1.34)
FMC_SDNRAS: mem (U3.18), stm (U1.59)
FMC_SDNWE: mem (U3.16), stm (U1.32)
IIC_SCL: mem (R20.1 U5.6), stm (J1.8 U1.45)
IIC_SDA: mem (R21.1 U5.5), stm (J1.7 U1.46)
LCD_B3: circuit (J3.24), stm (U1.154)
LCD_B4: circuit (J3.25), stm (U1.173)
LCD_B5: circuit (J3.26), stm (U1.174)
LCD_B6: circuit (J3.27), stm (U1.175)
LCD_B7: circuit (J3.28), stm (U1.176)
LCD_BL: circuit (J3.34), stm (J1.23 U1.163)
LCD_CLK: circuit (J3.30), stm (U1.111)
LCD_DE: circuit (J3.33), stm (U1.28)
LCD_G2: circuit (J3.14), stm (U1.128)
LCD_G3: circuit (J3.15), stm (U1.129)
LCD_G4: circuit (J3.16), stm (U1.130)
LCD_G5: circuit (J3.17), stm (U1.131)
LCD_G6: circuit (J3.18), stm (U1.132)
LCD_G7: circuit (J3.19), stm (U1.133)
LCD_HSYNC: circuit (J3.31), stm (U1.12)
LCD_R3: circuit (J3.6), stm (U1.86)
LCD_R4: circuit (J3.7), stm (U1.87)
LCD_R5: circuit (J3.8), stm (U1.88)
LCD_R6: circuit (J3.9), stm (J2.24 U1.89)
LCD_R7: circuit (J3.10), stm (U1.110)
LCD_VSYNC: circuit (J3.32), stm (U1.11)
LED0: circuit (DS0.2), stm (J1.57 U1.57)
PA0: circuit (WKUP.1), stm (U1.40)
PA9: circuit (P2.1), stm (U1.120)
PA10: circuit (P2.2), stm (U1.121)
PA11: circuit (R11.1), stm (U1.122)
PA12: circuit (R12.1), stm (U1.123)
PB2: mem (U6.6), stm (J1.55 U1.58)
PB6: mem (U6.1), stm (J1.24 U1.164)
PF6: mem (U6.7), stm (U1.24)
PF7: mem (U6.3), stm (U1.25)
PF8: mem (U6.5), stm (U1.26)
PF9: mem (U6.2), stm (U1.27)
PG3: circuit (J3.37), stm (U1.107)
PH6: circuit (J3.38), stm (J2.8 U1.83)
PH7: circuit (J3.39), stm (U1.84)
PI3: circuit (J3.36), stm (U1.134)
PI8: circuit (J3.35), stm (U1.7)
RESET: circuit (J3.40), stm (6 pins)
VREF+: circuit (R13.1), stm (J1.2)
